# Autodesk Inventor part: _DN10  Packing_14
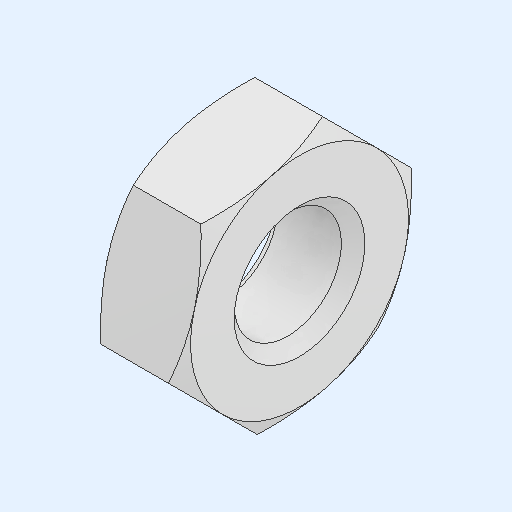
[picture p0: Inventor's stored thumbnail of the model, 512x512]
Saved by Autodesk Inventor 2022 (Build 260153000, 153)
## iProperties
Created: 2021-12
Part Number: _DN10  Packing_14
Material: Generico
Document SubType Name: Modeling
Designer: admin
Density: 1 g/cm^3
Appearance: Default
Author: admin
Revision Number: NONE
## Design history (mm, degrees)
feature "_DN10  Packing"
node "Solido1"
